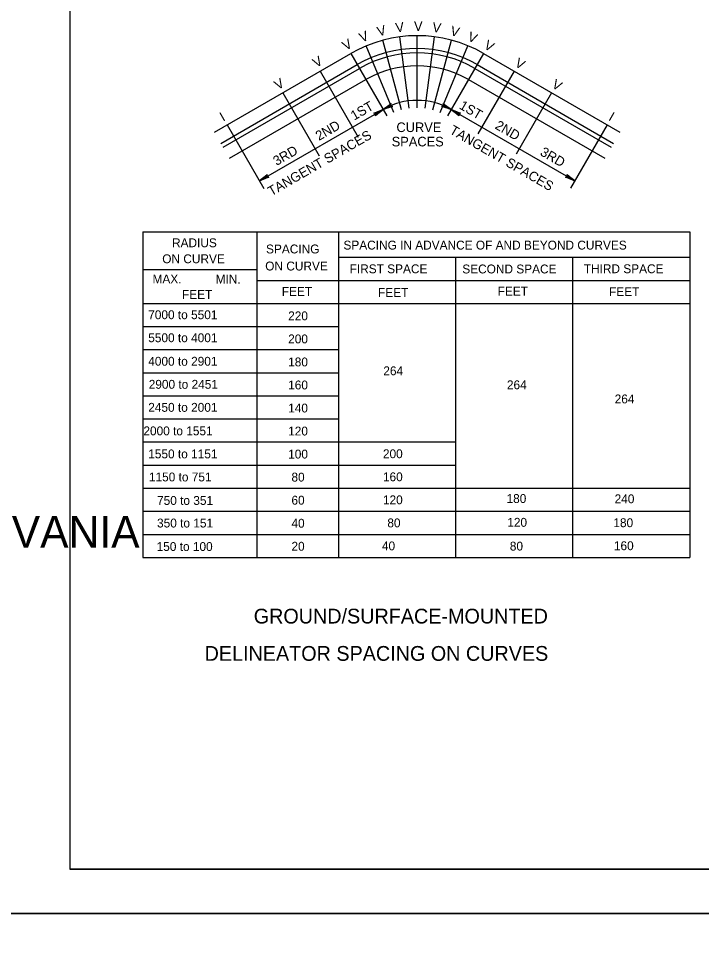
# Model space of a CAD drawing. Extents: x 640253 to 641999, y 298458 to 299646.
# Drawn here: x 641116.9 to 641348.1, y 299044.1 to 299354.5 of the extents above; entities that cross this region are included whole.
import ezdxf

# ---------------------------------------------------------------- set-up
doc = ezdxf.new("R2010")
doc.units = 0
for name, color, linetype in [('1', 7, 'Continuous'), ('2', 7, 'Continuous'), ('PLT-BNDY', 7, 'Continuous')]:
    doc.layers.add(name, color=color, linetype=linetype)

msp = doc.modelspace()

# ---------------------------------------------------------------- linework, layer by layer
at = {"layer": '1'}
for p, q in [((641134.31, 299630.63), (641134.31, 299066.63)), ((641920.31, 299066.63), (641134.31, 299066.63)), ((641134.31, 299066.63), (641720.31, 299066.63))]:
    msp.add_line(p, q, dxfattribs=at)
at = {"layer": '2'}
for p, q in [((641246.48, 299323.51), (641240.18, 299347.05)), ((641249.11, 299324.03), (641245.92, 299348.19)), ((641251.79, 299324.21), (641251.79, 299348.59)), ((641254.48, 299324.03), (641257.65, 299348.21)), ((641257.1, 299323.51), (641263.4, 299347.07)), ((641243.92, 299322.66), (641234.6, 299345.17)), ((641259.64, 299322.65), (641268.97, 299345.17)), ((641183.19, 299315.93), (641229.35, 299342.57)), ((641229.35, 299342.57), (641241.52, 299321.45)), ((641274.23, 299342.57), (641262.06, 299321.45)), ((641274.23, 299342.57), (641320.38, 299315.93)), ((641185.36, 299312.16), (641231.51, 299338.8)), ((641186.11, 299310.88), (641232.26, 299337.52)), ((641271.31, 299337.52), (641317.47, 299310.88)), ((641272.06, 299338.8), (641318.21, 299312.16)), ((641188.28, 299307.11), (641234.43, 299333.75)), ((641219, 299336.62), (641231.86, 299314.3)), ((641269.15, 299333.75), (641315.3, 299307.11)), ((641284.57, 299336.62), (641272.34, 299315.39)), ((641206.31, 299329.29), (641218.65, 299307.91)), ((641297.26, 299329.29), (641285.29, 299308.52)), ((641198.45, 299299.49), (641240.28, 299323.63)), ((641263.31, 299323.63), (641305.13, 299299.49)), ((641187.51, 299318.46), (641199.96, 299296.87)), ((641316.06, 299318.46), (641303.69, 299296.99)), ((641159.01, 299282.19), (641159.01, 299172.09)), ((641159.01, 299282.19), (641344.02, 299282.19)), ((641197.5, 299282.19), (641197.5, 299172.09)), ((641225.15, 299282.19), (641225.15, 299172.09)), ((641344.02, 299282.19), (641344.02, 299172.09)), ((641225.15, 299273.63), (641344.02, 299273.63)), ((641229.96, 299273.63), (641229.96, 299273.63)), ((641264.75, 299273.63), (641264.75, 299172.09)), ((641265.3, 299273.63), (641265.3, 299273.63)), ((641300.64, 299273.63), (641300.64, 299273.63)), ((641304.35, 299273.63), (641304.35, 299172.09)), ((641335.98, 299273.63), (641335.98, 299273.63)), ((641159.01, 299269.53), (641197.57, 299269.53)), ((641197.5, 299265.82), (641344.02, 299265.82)), ((641159.01, 299258.01), (641344.02, 299258.01)), ((641159.01, 299250.19), (641225.15, 299250.19)), ((641159.01, 299242.38), (641225.15, 299242.38)), ((641159.01, 299234.57), (641225.15, 299234.57)), ((641159.01, 299226.76), (641225.15, 299226.76)), ((641159.01, 299218.95), (641225.15, 299218.95)), ((641159.01, 299211.14), (641264.75, 299211.14)), ((641159.01, 299203.33), (641264.75, 299203.33)), ((641159.01, 299195.52), (641344.02, 299195.52)), ((641159.01, 299187.71), (641344.02, 299187.71)), ((641159.01, 299179.9), (641344.02, 299179.9)), ((641159.01, 299172.09), (641344.02, 299172.09))]:
    msp.add_line(p, q, dxfattribs=at)
for points in [[(641243.27, 299324.73), (641243.06, 299324.87), (641240.28, 299323.63), (641243.27, 299324.73), (641243.47, 299324.68), (641240.28, 299323.63), (641242.92, 299325.14), (641242.9, 299325.4), (641240.28, 299323.63), (641242.99, 299325.61), (641242.9, 299325.4)], [(641260.67, 299325.42), (641260.67, 299325.16), (641263.31, 299323.63), (641260.67, 299325.42), (641260.61, 299325.61), (641263.31, 299323.63), (641260.54, 299324.87), (641260.35, 299324.73), (641263.31, 299323.63), (641260.12, 299324.66), (641260.35, 299324.73)], [(641237.35, 299322.4), (641237.57, 299322.26), (641240.28, 299323.63), (641237.35, 299322.4), (641237.14, 299322.44), (641240.28, 299323.63), (641237.73, 299321.99), (641237.75, 299321.74), (641240.28, 299323.63), (641237.68, 299321.52), (641237.75, 299321.74)], [(641265.85, 299321.71), (641265.86, 299321.97), (641263.31, 299323.63), (641265.85, 299321.71), (641265.92, 299321.52), (641263.31, 299323.63), (641266.02, 299322.24), (641266.23, 299322.38), (641263.31, 299323.63), (641266.45, 299322.44), (641266.23, 299322.38)], [(641201.38, 299300.72), (641201.16, 299300.86), (641198.45, 299299.49), (641201.38, 299300.72), (641201.59, 299300.69), (641198.45, 299299.49), (641201, 299301.14), (641200.98, 299301.38), (641198.45, 299299.49), (641201.05, 299301.61), (641200.98, 299301.38)], [(641302.59, 299301.42), (641302.57, 299301.16), (641305.13, 299299.49), (641302.59, 299301.42), (641302.52, 299301.61), (641305.13, 299299.49), (641302.42, 299300.88), (641302.21, 299300.74), (641305.13, 299299.49), (641301.99, 299300.69), (641302.21, 299300.74)]]:
    msp.add_lwpolyline(points, dxfattribs=at)
for radius in [44.9, 40.55, 39.07, 34.71, 23.03]:
    msp.add_arc((641251.8, 299303.69), radius, 60.0122, 120.0089, dxfattribs=at)
at = {"layer": 'PLT-BNDY'}
for points in [[(641094.31, 299645.63), (641935.31, 299645.63), (641935.31, 299051.63), (641094.31, 299051.63)], [(641094.31, 299051.63), (641935.31, 299051.63), (641935.31, 298457.63), (641094.31, 298457.63)]]:
    msp.add_lwpolyline(points, close=True, dxfattribs=at)

# ---------------------------------------------------------------- texts
at = {"layer": '1'}
msp.add_text('COMMONWEALTH OF PENNSYLVANIA', height=10.7828, dxfattribs=at).set_placement((640891.9, 299175.36))
at = {"layer": '2'}
for s, height, rotation, p in [('V', 3.25, 7.491, (641244.67, 299349.65)), ('V', 3.25, 359.9889, (641250.73, 299350.19)), ('V', 3.25, 352.4868, (641256.8, 299349.93)), ('V', 3.25, 22.4951, (641233.02, 299346.25)), ('V', 3.25, 14.993, (641238.73, 299348.33)), ('V', 3.25, 344.9847, (641262.79, 299348.87)), ('V', 3.25, 337.4827, (641268.59, 299347.05)), ('V', 3.25, 29.9972, (641227.63, 299343.44)), ('V', 3.25, 330.0028, (641274.13, 299344.5)), ('V', 3.25, 330.0028, (641274.13, 299344.5)), ('V', 3.25, 29.9972, (641217.61, 299337.66)), ('V', 3.25, 330.0028, (641284.57, 299338.46)), ('V', 3.25, 29.9972, (641204.63, 299330.16)), ('V', 3.25, 330.0028, (641297.09, 299331.24)), ('1ST', 3.246, 29.9926, (641230.49, 299319.85)), ('1ST', 3.246, 329.9971, (641265.76, 299324.09)), ('I', 3.25, 29.9972, (641186.13, 299319.49)), ('I', 3.25, 330.0028, (641316.3, 299320.15)), ('2ND', 3.246, 29.9926, (641218.58, 299312.98)), ('TANGENT SPACES', 3.2458, 330, (641262.48, 299315.7)), ('2ND', 3.246, 329.9971, (641277.86, 299317.33)), ('TANGENT SPACES', 3.2458, 30, (641202.46, 299294.25)), ('3RD', 3.246, 29.9926, (641204.23, 299304.49)), ('3RD', 3.246, 329.9971, (641293.13, 299308.34))]:
    msp.add_text(s, height=height, rotation=rotation, dxfattribs=at).set_placement(p)
for s, height, p in [('CURVE', 3.246, (641244.79, 299316)), ('SPACES', 3.246, (641243.18, 299311.14)), ('RADIUS', 3, (641168.86, 299277.03)), ('SPACING', 3, (641200.67, 299274.94)), ('SPACING IN ADVANCE OF AND BEYOND CURVES', 3, (641226.86, 299276.25)), ('ON CURVE', 3, (641165.55, 299271.62)), ('ON CURVE', 3, (641200.39, 299269.17)), ('FIRST SPACE', 3, (641228.96, 299268.23)), ('SECOND SPACE', 3, (641267.07, 299268.17)), ('THIRD SPACE', 3, (641308.18, 299268.25)), ('MAX.', 3, (641162.26, 299264.8)), ('MIN.', 3, (641183.62, 299264.74)), ('FEET', 3, (641172.22, 299259.57)), ('FEET', 3, (641206.01, 299260.58)), ('FEET', 3, (641238.57, 299260.22)), ('FEET', 3, (641279.03, 299260.67)), ('FEET', 3, (641316.74, 299260.49)), ('7000 to 5501', 3, (641160.8, 299252.69)), ('220', 3, (641208.15, 299252.31)), ('5500 to 4001', 3, (641160.81, 299244.9)), ('200', 3, (641208.15, 299244.52)), ('4000 to 2901', 3, (641160.81, 299236.95)), ('180', 3, (641208.15, 299236.72)), ('264', 3, (641240.35, 299233.72)), ('2900 to 2451', 3, (641160.97, 299229.15)), ('160', 3, (641208.15, 299228.93)), ('264', 3, (641282.17, 299228.98)), ('264', 3, (641318.63, 299224.2)), ('2450 to 2001', 3, (641160.81, 299221.36)), ('140', 3, (641208.15, 299221.13)), (' 2000 to 1551', 3, (641158.06, 299213.4)), ('120', 3, (641208.15, 299213.34)), ('1550 to 1151', 3, (641160.81, 299205.61)), ('100', 3, (641208.15, 299205.54)), ('200', 3, (641240.22, 299205.66)), ('1150 to 751', 3, (641161.04, 299197.81)), (' 80', 3, (641208.15, 299197.75)), ('160', 3, (641240.22, 299197.86)), ('750 to 351', 3, (641163.79, 299189.86)), (' 60', 3, (641208.15, 299189.95)), ('120', 3, (641240.22, 299190.07)), ('180', 3, (641282.04, 299190.51)), ('240', 3, (641318.61, 299190.42)), ('350 to 151', 3, (641163.79, 299182.22)), (' 40', 3, (641208.15, 299182.16)), ('80', 3, (641241.71, 299182.27)), ('120', 3, (641282.29, 299182.46)), ('180', 3, (641318.19, 299182.33)), ('150 to 100', 3, (641163.64, 299174.27)), (' 20', 3, (641208.15, 299174.36)), (' 40', 3, (641238.76, 299174.48)), (' 80', 3, (641282.04, 299174.41)), ('160', 3, (641318.37, 299174.54)), ('GROUND/SURFACE-MOUNTED', 5, (641196.5, 299149.73)), ('DELINEATOR SPACING ON CURVES', 5, (641179.88, 299137.11))]:
    msp.add_text(s, height=height, dxfattribs=at).set_placement(p)

doc.saveas('drawing.dxf')
